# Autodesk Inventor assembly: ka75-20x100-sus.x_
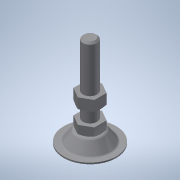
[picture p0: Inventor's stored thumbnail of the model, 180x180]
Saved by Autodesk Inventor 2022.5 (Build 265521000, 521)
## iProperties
Part Number: ka75-20x100-sus.x_
Material: 一般
Document SubType Name: Assembly
Designer: ImaoCorp
Sending System: SOLIDWORKS 2017-2017317
MC: AMD64
MC_MODEL: Intel64 Family 6 Model 60 Stepping 3, GenuineIntel
OS: Windows_NT
FRU: Parasolid Version 29.0, build 201,  4-17-2017
FORMAT: text
GUISE: transmit
KEY: ka75-20x100-sus
FILE: ka75-20x100-sus.x_t
DATE: Mon Jul 01 17:42:21 2019
Author: ImaoCorp
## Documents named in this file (3)
- X:\14_SW2022-Inv2022\00_全2023-1023新製品(TCC)まで\k\ka75-20x100-sus\KA75-20X100-SUS.iam
- X:\14_SW2022-Inv2022\00_全2023-1023新製品(TCC)まで\k\ka75-20x100-sus\ka75-20x100-sus_01.ipt
- X:\14_SW2022-Inv2022\00_全2023-1023新製品(TCC)まで\k\ka75-20x100-sus\ka75-20x100-sus_02.ipt
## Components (2 placed, 2 different names)
1. ka75-20x100-sus_01
2. ka75-20x100-sus_02
